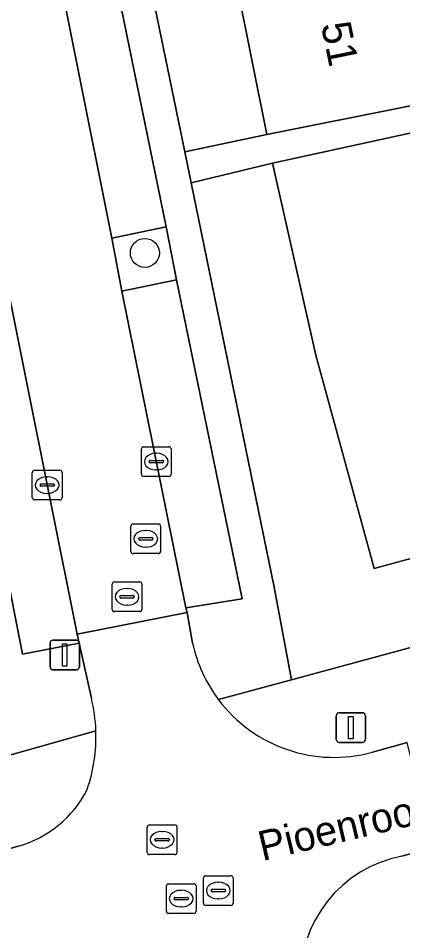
# Model space of a CAD drawing. Extents: x 162250 to 162661, y 380743 to 381606.
# Drawn here: x 162527.18 to 162540.15, y 380962.98 to 380993.72 of the extents above; entities that cross this region are included whole.
import ezdxf

# ---------------------------------------------------------------- set-up
doc = ezdxf.new("R2010")
doc.units = 0
for name, color, linetype in [('IMGEO_Boom', 7, 'Continuous'), ('IMGEO_Erf', 7, 'Continuous'), ('IMGEO_Groenvoorziening', 7, 'Continuous'), ('IMGEO_Kolk', 7, 'Continuous'), ('IMGEO_Lichtmast', 7, 'Continuous'), ('IMGEO_Openbare_ruimte_label', 7, 'Continuous'), ('IMGEO_Pand', 7, 'Continuous'), ('IMGEO_Pand_nummerreeks', 7, 'Continuous'), ('IMGEO_Parkeervlak_open', 7, 'Continuous'), ('IMGEO_Rijbaan_lokaal_open', 7, 'Continuous'), ('IMGEO_Rioolput', 7, 'Continuous'), ('IMGEO_Voetpad_open', 7, 'Continuous'), ('IMGEO_Woonerf_open', 7, 'Continuous')]:
    doc.layers.add(name, color=color, linetype=linetype)

msp = doc.modelspace()

# ---------------------------------------------------------------- linework, layer by layer
at = {"layer": 'IMGEO_Boom'}
msp.add_circle((162531.454, 380985.813), 0.489, dxfattribs=at)
at = {"layer": 'IMGEO_Erf'}
for points in [[(162522.143, 381040.929), (162529.31, 381005.466), (162530.582, 381000), (162532.797, 380989.217), (162535.562, 380989.8), (162534.55, 380994.844), (162533.553, 380999.816), (162533.516, 381000), (162532.586, 381004.64), (162531.573, 381009.689), (162531.896, 381009.754), (162530.915, 381014.622), (162529.951, 381019.403), (162528.936, 381024.444), (162528.01, 381029.037), (162527.714, 381028.978), (162526.67, 381034.16)], [(162584.66, 380993.815), (162584.129, 380993.669), (162585.707, 380987.946), (162575.368, 380985.129), (162568.351, 380983.216), (162563.435, 380981.877), (162558.558, 380980.548), (162558.309, 380980.48), (162558.21, 380980.844), (162553.71, 380979.617), (162548.909, 380978.309), (162549.03, 380977.865), (162544.039, 380976.505), (162543.728, 380976.42), (162539.181, 380975.181), (162537.223, 380982.367), (162535.754, 380988.839), (162533.01, 380988.176), (162535.808, 380974.554), (162536.403, 380971.431), (162590.435, 380986.089)]]:
    msp.add_lwpolyline(points, dxfattribs=at)
at = {"layer": 'IMGEO_Groenvoorziening'}
msp.add_lwpolyline([(162532.173, 380986.691), (162530.338, 380986.31), (162530.682, 380984.53), (162532.52, 380984.907)], close=True, dxfattribs=at)
at = {"layer": 'IMGEO_Kolk'}
for p, q in [((162531.338, 380978.358), (162531.338, 380979.21)), ((162531.413, 380979.284), (162532.265, 380979.284)), ((162532.339, 380979.21), (162532.339, 380978.358)), ((162531.597, 380978.778), (162531.597, 380978.79)), ((162531.64, 380978.827), (162532.038, 380978.827)), ((162531.826, 380979.064), (162531.851, 380979.064)), ((162532.081, 380978.79), (162532.081, 380978.778)), ((162527.735, 380978.495), (162528.587, 380978.495)), ((162532.035, 380978.741), (162531.637, 380978.741)), ((162531.849, 380978.504), (162531.824, 380978.504)), ((162527.66, 380977.569), (162527.66, 380978.421)), ((162528.148, 380978.275), (162528.173, 380978.275)), ((162528.661, 380978.421), (162528.661, 380977.569)), ((162532.265, 380978.284), (162531.413, 380978.284)), ((162527.919, 380977.989), (162527.919, 380978.001)), ((162528.357, 380977.952), (162527.959, 380977.952)), ((162527.962, 380978.038), (162528.36, 380978.038)), ((162528.403, 380978.001), (162528.403, 380977.989)), ((162528.171, 380977.715), (162528.146, 380977.715)), ((162528.587, 380977.495), (162527.735, 380977.495))]:
    msp.add_line(p, q, dxfattribs=at)
for points in [[(162531.338, 380978.358), (162531.338, 380979.21)], [(162531.413, 380979.284), (162532.265, 380979.284)], [(162532.339, 380979.21), (162532.339, 380978.358)], [(162527.735, 380978.495), (162528.587, 380978.495)], [(162527.66, 380977.569), (162527.66, 380978.421)], [(162528.661, 380978.421), (162528.661, 380977.569)], [(162532.265, 380978.284), (162531.413, 380978.284)], [(162528.587, 380977.495), (162527.735, 380977.495)]]:
    msp.add_lwpolyline(points, dxfattribs=at)
for centre, radius, start, end in [((162531.415, 380979.208), 0.0765, 91.552, 178.448), ((162531.415, 380979.208), 0.0765, 91.552, 178.448), ((162532.263, 380979.208), 0.0765, 1.552, 88.448), ((162532.263, 380979.208), 0.0765, 1.552, 88.448), ((162531.637, 380978.787), 0.0403, 85.8775, 175.7526), ((162532.042, 380978.789), 0.0386, 1.7309, 96.639), ((162527.737, 380978.419), 0.0765, 91.552, 178.448), ((162527.737, 380978.419), 0.0765, 91.552, 178.448), ((162528.585, 380978.419), 0.0765, 1.552, 88.448), ((162528.585, 380978.419), 0.0765, 1.552, 88.448), ((162531.634, 380978.777), 0.0366, 178.938, 274.7102), ((162532.038, 380978.784), 0.043, 264.8664, 352.4533), ((162531.415, 380978.36), 0.0765, 181.552, 268.448), ((162531.415, 380978.36), 0.0765, 181.552, 268.448), ((162532.263, 380978.36), 0.0765, 271.552, 358.448), ((162532.263, 380978.36), 0.0765, 271.552, 358.448), ((162527.959, 380977.998), 0.0403, 85.8775, 175.7526), ((162527.956, 380977.988), 0.0366, 178.938, 274.7102), ((162528.36, 380977.995), 0.043, 264.8664, 352.4533), ((162528.364, 380978), 0.0386, 1.7309, 96.639), ((162527.737, 380977.571), 0.0765, 181.552, 268.448), ((162527.737, 380977.571), 0.0765, 181.552, 268.448), ((162528.585, 380977.571), 0.0765, 271.552, 358.448), ((162528.585, 380977.571), 0.0765, 271.552, 358.448)]:
    msp.add_arc(centre, radius, start, end, dxfattribs=at)
for centre, major_axis, ratio, start_param, end_param in [((162531.825, 380978.784), (-0.387, 0.002), 0.722429, 4.712389, 7.853982), ((162531.85, 380978.784), (-0.39, 0.002), 0.717154, 1.570796, 4.712389), ((162528.147, 380977.995), (-0.387, 0.002), 0.722429, 4.712389, 7.853982), ((162528.172, 380977.995), (-0.39, 0.002), 0.717154, 1.570796, 4.712389)]:
    msp.add_ellipse(centre, major_axis=major_axis, ratio=ratio, start_param=start_param, end_param=end_param, dxfattribs=at)
at = {"layer": 'IMGEO_Lichtmast'}
for p, q in [((162528.256, 380971.872), (162528.256, 380972.672)), ((162528.256, 380972.672), (162528.256, 380971.872)), ((162528.356, 380972.772), (162529.146, 380972.772)), ((162529.146, 380972.772), (162528.356, 380972.772)), ((162529.246, 380972.672), (162529.246, 380971.872)), ((162529.246, 380971.872), (162529.246, 380972.672)), ((162529.146, 380971.772), (162528.356, 380971.772)), ((162528.356, 380971.772), (162529.146, 380971.772)), ((162537.903, 380969.425), (162537.903, 380970.225)), ((162537.903, 380970.225), (162537.903, 380969.425)), ((162538.003, 380970.325), (162538.793, 380970.325)), ((162538.793, 380970.325), (162538.003, 380970.325)), ((162538.893, 380970.225), (162538.893, 380969.425)), ((162538.893, 380969.425), (162538.893, 380970.225)), ((162538.793, 380969.325), (162538.003, 380969.325)), ((162538.003, 380969.325), (162538.793, 380969.325))]:
    msp.add_line(p, q, dxfattribs=at)
for points in [[(162528.676, 380972.647), (162528.826, 380972.647), (162528.826, 380971.897), (162528.676, 380971.897), (162528.676, 380972.647)], [(162538.323, 380970.2), (162538.473, 380970.2), (162538.473, 380969.45), (162538.323, 380969.45), (162538.323, 380970.2)]]:
    msp.add_lwpolyline(points, dxfattribs=at)
for centre, start, end in [((162528.356, 380972.672), 90, 180), ((162528.356, 380972.672), 90, 180), ((162529.146, 380972.672), 0, 90), ((162529.146, 380972.672), 360, 90), ((162528.356, 380971.872), 180, 270), ((162528.356, 380971.872), 180, 270), ((162529.146, 380971.872), 270, 0), ((162529.146, 380971.872), 270, 0), ((162538.003, 380970.225), 90, 180), ((162538.003, 380970.225), 90, 180), ((162538.793, 380970.225), 0, 90), ((162538.793, 380970.225), 360, 90), ((162538.003, 380969.425), 180, 270), ((162538.003, 380969.425), 180, 270), ((162538.793, 380969.425), 270, 0), ((162538.793, 380969.425), 270, 0)]:
    msp.add_arc(centre, 0.1, start, end, dxfattribs=at)
at = {"layer": 'IMGEO_Pand'}
for points in [[(162549.164, 380997.798), (162547.269, 380997.415), (162545.854, 380997.129), (162534.55, 380994.844), (162535.562, 380989.8), (162540.466, 380990.779), (162542.944, 380991.274), (162542.426, 380993.869), (162547.281, 380994.839), (162547.764, 380994.935), (162549.66, 380995.314)], [(162544.039, 380976.505), (162540.641, 380989.9), (162535.754, 380988.839), (162537.223, 380982.367), (162539.181, 380975.181), (162543.728, 380976.42)]]:
    msp.add_lwpolyline(points, close=True, dxfattribs=at)
at = {"layer": 'IMGEO_Parkeervlak_open'}
for points in [[(162530.338, 380986.31), (162532.173, 380986.691), (162529.751, 380998.475), (162527.982, 380998.093)], [(162529.238, 380972.673), (162529.173, 380972.977), (162526.498, 380986.245), (162524.664, 380985.878), (162527.328, 380972.293)], [(162534.731, 380974.16), (162532.52, 380984.907), (162530.682, 380984.53), (162532.831, 380973.854)]]:
    msp.add_lwpolyline(points, close=True, dxfattribs=at)
at = {"layer": 'IMGEO_Rijbaan_lokaal_open'}
for points in [[(162533.062, 380972.669), (162532.879, 380973.707), (162529.173, 380972.977), (162529.238, 380972.673), (162529.652, 380970.821)], [(162541.171, 380965.788), (162540.292, 380969.32), (162539.13, 380968.997)], [(162527.185, 380965.829), (162526.007, 380965.497), (162527.124, 380961.813), (162528.084, 380962.039)], [(162540.122, 380965.489), (162541.171, 380965.788)]]:
    msp.add_lwpolyline(points, dxfattribs=at)
for centre, radius, start, end in [((162537.82, 380973.7), 4.869, 192.2264, 217.0601), ((162524.301, 380969.522), 5.506, 2.0434, 13.6491), ((162537.835, 380973.707), 4.885, 217.0191, 285.3715), ((162524.291, 380969.532), 5.516, 341.0437, 1.9344), ((162526.182, 380969.415), 3.724, 285.6217, 333.2626), ((162540.883, 380961.376), 4.183, 100.4804, 182.5843)]:
    msp.add_arc(centre, radius, start, end, dxfattribs=at)
at = {"layer": 'IMGEO_Rioolput'}
for p, q in [((162531.06, 380976.684), (162531.912, 380976.684)), ((162530.985, 380975.758), (162530.985, 380976.61)), ((162531.473, 380976.464), (162531.498, 380976.464)), ((162531.986, 380976.61), (162531.986, 380975.758)), ((162531.244, 380976.178), (162531.244, 380976.19)), ((162531.682, 380976.141), (162531.284, 380976.141)), ((162531.287, 380976.227), (162531.685, 380976.227)), ((162531.728, 380976.19), (162531.728, 380976.178)), ((162531.496, 380975.904), (162531.471, 380975.904)), ((162531.912, 380975.684), (162531.06, 380975.684)), ((162530.354, 380973.804), (162530.354, 380974.656)), ((162530.429, 380974.73), (162531.281, 380974.73)), ((162530.842, 380974.51), (162530.867, 380974.51)), ((162531.355, 380974.656), (162531.355, 380973.804)), ((162530.613, 380974.224), (162530.613, 380974.236)), ((162531.051, 380974.187), (162530.653, 380974.187)), ((162530.656, 380974.273), (162531.054, 380974.273)), ((162531.097, 380974.236), (162531.097, 380974.224)), ((162530.865, 380973.95), (162530.84, 380973.95)), ((162531.281, 380973.73), (162530.429, 380973.73)), ((162531.611, 380966.549), (162532.463, 380966.549)), ((162531.536, 380965.623), (162531.536, 380966.475)), ((162532.024, 380966.329), (162532.049, 380966.329)), ((162532.537, 380966.475), (162532.537, 380965.623)), ((162531.795, 380966.043), (162531.795, 380966.055)), ((162532.233, 380966.006), (162531.835, 380966.006)), ((162531.838, 380966.092), (162532.236, 380966.092)), ((162532.279, 380966.055), (162532.279, 380966.043)), ((162532.047, 380965.769), (162532.022, 380965.769)), ((162532.463, 380965.549), (162531.611, 380965.549)), ((162533.429, 380963.909), (162533.429, 380964.761)), ((162533.504, 380964.835), (162534.356, 380964.835)), ((162534.43, 380964.761), (162534.43, 380963.909)), ((162532.178, 380963.638), (162532.178, 380964.49)), ((162532.253, 380964.564), (162533.105, 380964.564)), ((162532.666, 380964.344), (162532.691, 380964.344)), ((162533.179, 380964.49), (162533.179, 380963.638)), ((162533.688, 380964.329), (162533.688, 380964.341)), ((162533.731, 380964.378), (162534.129, 380964.378)), ((162533.917, 380964.615), (162533.942, 380964.615)), ((162534.172, 380964.341), (162534.172, 380964.329)), ((162532.437, 380964.058), (162532.437, 380964.07)), ((162532.48, 380964.107), (162532.878, 380964.107)), ((162532.921, 380964.07), (162532.921, 380964.058)), ((162534.126, 380964.292), (162533.728, 380964.292)), ((162533.94, 380964.055), (162533.915, 380964.055)), ((162532.875, 380964.021), (162532.477, 380964.021)), ((162532.689, 380963.784), (162532.664, 380963.784)), ((162534.356, 380963.835), (162533.504, 380963.835)), ((162533.105, 380963.564), (162532.253, 380963.564))]:
    msp.add_line(p, q, dxfattribs=at)
for points in [[(162531.06, 380976.684), (162531.912, 380976.684)], [(162530.985, 380975.758), (162530.985, 380976.61)], [(162531.986, 380976.61), (162531.986, 380975.758)], [(162531.912, 380975.684), (162531.06, 380975.684)], [(162530.354, 380973.804), (162530.354, 380974.656)], [(162530.429, 380974.73), (162531.281, 380974.73)], [(162531.355, 380974.656), (162531.355, 380973.804)], [(162531.281, 380973.73), (162530.429, 380973.73)], [(162531.611, 380966.549), (162532.463, 380966.549)], [(162531.536, 380965.623), (162531.536, 380966.475)], [(162532.537, 380966.475), (162532.537, 380965.623)], [(162532.463, 380965.549), (162531.611, 380965.549)], [(162533.429, 380963.909), (162533.429, 380964.761)], [(162533.504, 380964.835), (162534.356, 380964.835)], [(162534.43, 380964.761), (162534.43, 380963.909)], [(162532.178, 380963.638), (162532.178, 380964.49)], [(162532.253, 380964.564), (162533.105, 380964.564)], [(162533.179, 380964.49), (162533.179, 380963.638)], [(162534.356, 380963.835), (162533.504, 380963.835)], [(162533.105, 380963.564), (162532.253, 380963.564)]]:
    msp.add_lwpolyline(points, dxfattribs=at)
for centre, radius, start, end in [((162531.062, 380976.608), 0.0765, 91.552, 178.448), ((162531.062, 380976.608), 0.0765, 91.552, 178.448), ((162531.91, 380976.608), 0.0765, 1.552, 88.448), ((162531.91, 380976.608), 0.0765, 1.552, 88.448), ((162531.284, 380976.187), 0.0403, 85.8775, 175.7526), ((162531.281, 380976.177), 0.0366, 178.938, 274.7102), ((162531.685, 380976.184), 0.043, 264.8664, 352.4533), ((162531.689, 380976.189), 0.0386, 1.7309, 96.639), ((162531.062, 380975.76), 0.0765, 181.552, 268.448), ((162531.062, 380975.76), 0.0765, 181.552, 268.448), ((162531.91, 380975.76), 0.0765, 271.552, 358.448), ((162531.91, 380975.76), 0.0765, 271.552, 358.448), ((162530.431, 380974.654), 0.0765, 91.552, 178.448), ((162530.431, 380974.654), 0.0765, 91.552, 178.448), ((162531.279, 380974.654), 0.0765, 1.552, 88.448), ((162531.279, 380974.654), 0.0765, 1.552, 88.448), ((162530.653, 380974.233), 0.0403, 85.8775, 175.7526), ((162530.65, 380974.223), 0.0366, 178.938, 274.7102), ((162531.054, 380974.23), 0.043, 264.8664, 352.4533), ((162531.058, 380974.235), 0.0386, 1.7309, 96.639), ((162530.431, 380973.806), 0.0765, 181.552, 268.448), ((162530.431, 380973.806), 0.0765, 181.552, 268.448), ((162531.279, 380973.806), 0.0765, 271.552, 358.448), ((162531.279, 380973.806), 0.0765, 271.552, 358.448), ((162531.613, 380966.473), 0.0765, 91.552, 178.448), ((162531.613, 380966.473), 0.0765, 91.552, 178.448), ((162532.461, 380966.473), 0.0765, 1.552, 88.448), ((162532.461, 380966.473), 0.0765, 1.552, 88.448), ((162531.835, 380966.052), 0.0403, 85.8775, 175.7526), ((162531.832, 380966.042), 0.0366, 178.938, 274.7102), ((162532.236, 380966.049), 0.043, 264.8664, 352.4533), ((162532.24, 380966.054), 0.0386, 1.7309, 96.639), ((162531.613, 380965.625), 0.0765, 181.552, 268.448), ((162531.613, 380965.625), 0.0765, 181.552, 268.448), ((162532.461, 380965.625), 0.0765, 271.552, 358.448), ((162532.461, 380965.625), 0.0765, 271.552, 358.448), ((162533.506, 380964.759), 0.0765, 91.552, 178.448), ((162533.506, 380964.759), 0.0765, 91.552, 178.448), ((162534.354, 380964.759), 0.0765, 1.552, 88.448), ((162534.354, 380964.759), 0.0765, 1.552, 88.448), ((162532.255, 380964.488), 0.0765, 91.552, 178.448), ((162532.255, 380964.488), 0.0765, 91.552, 178.448), ((162533.103, 380964.488), 0.0765, 1.552, 88.448), ((162533.103, 380964.488), 0.0765, 1.552, 88.448), ((162533.728, 380964.338), 0.0403, 85.8775, 175.7526), ((162534.133, 380964.34), 0.0386, 1.7309, 96.639), ((162532.477, 380964.067), 0.0403, 85.8775, 175.7526), ((162532.474, 380964.057), 0.0366, 178.938, 274.7102), ((162532.878, 380964.064), 0.043, 264.8664, 352.4533), ((162532.882, 380964.069), 0.0386, 1.7309, 96.639), ((162533.725, 380964.328), 0.0366, 178.938, 274.7102), ((162534.129, 380964.335), 0.043, 264.8664, 352.4533), ((162533.506, 380963.911), 0.0765, 181.552, 268.448), ((162533.506, 380963.911), 0.0765, 181.552, 268.448), ((162534.354, 380963.911), 0.0765, 271.552, 358.448), ((162534.354, 380963.911), 0.0765, 271.552, 358.448), ((162532.255, 380963.64), 0.0765, 181.552, 268.448), ((162532.255, 380963.64), 0.0765, 181.552, 268.448), ((162533.103, 380963.64), 0.0765, 271.552, 358.448), ((162533.103, 380963.64), 0.0765, 271.552, 358.448)]:
    msp.add_arc(centre, radius, start, end, dxfattribs=at)
for centre, major_axis, ratio, start_param, end_param in [((162531.472, 380976.184), (-0.387, 0.002), 0.722429, 4.712389, 7.853982), ((162531.497, 380976.184), (-0.39, 0.002), 0.717154, 1.570796, 4.712389), ((162530.841, 380974.23), (-0.387, 0.002), 0.722429, 4.712389, 7.853982), ((162530.866, 380974.23), (-0.39, 0.002), 0.717154, 1.570796, 4.712389), ((162532.023, 380966.049), (-0.387, 0.002), 0.722429, 4.712389, 7.853982), ((162532.048, 380966.049), (-0.39, 0.002), 0.717154, 1.570796, 4.712389), ((162532.665, 380964.064), (-0.387, 0.002), 0.722429, 4.712389, 7.853982), ((162532.69, 380964.064), (-0.39, 0.002), 0.717154, 1.570796, 4.712389), ((162533.916, 380964.335), (-0.387, 0.002), 0.722429, 4.712389, 7.853982), ((162533.941, 380964.335), (-0.39, 0.002), 0.717154, 1.570796, 4.712389)]:
    msp.add_ellipse(centre, major_axis=major_axis, ratio=ratio, start_param=start_param, end_param=end_param, dxfattribs=at)
at = {"layer": 'IMGEO_Voetpad_open'}
for points in [[(162535.808, 380974.554), (162533.01, 380988.176), (162532.797, 380989.217), (162530.582, 381000), (162529.31, 381005.466), (162522.143, 381040.929), (162522.087, 381041.214), (162521.287, 381041.063), (162521.648, 381039.309), (162523.995, 381027.547), (162524.343, 381025.754), (162526.697, 381013.911), (162527.071, 381012.154), (162529.44, 381000.334), (162529.751, 380998.475), (162532.173, 380986.691), (162532.52, 380984.907), (162534.731, 380974.16), (162532.831, 380973.854), (162532.879, 380973.707), (162533.062, 380972.669)], [(162514.276, 381037.726), (162513.922, 381039.54), (162512.477, 381039.235), (162520.3, 381000), (162523.029, 380986.937), (162523.272, 380985.775), (162525.511, 380975.056), (162526.18, 380971.982), (162526.854, 380968.89), (162529.804, 380969.718)], [(162529.652, 380970.821), (162529.238, 380972.673), (162527.328, 380972.293), (162524.664, 380985.878), (162526.498, 380986.245), (162526.262, 380987.458), (162524.476, 380987.064), (162514.276, 381037.726)], [(162590.435, 380986.089), (162536.403, 380971.431), (162533.935, 380970.766)], [(162533.935, 380970.766), (162536.403, 380971.431), (162535.808, 380974.554)], [(162529.804, 380969.718), (162526.854, 380968.89), (162499.174, 380961.297), (162498.385, 380964.311)], [(162539.13, 380968.997), (162540.292, 380969.32)], [(162523.548, 380964.83), (162526.007, 380965.497), (162527.185, 380965.829)], [(162541.171, 380965.788), (162540.122, 380965.489)]]:
    msp.add_lwpolyline(points, dxfattribs=at)
msp.add_lwpolyline([(162552.705, 380992.782), (162557.567, 380993.649), (162560.053, 380994.327), (162562.41, 380994.969), (162564.759, 380995.716), (162564.606, 380996.74), (162556.31, 380994.716), (162555.014, 380994.529), (162552.05, 380993.767), (162542.944, 380991.274), (162540.466, 380990.779), (162535.562, 380989.8), (162532.797, 380989.217), (162533.01, 380988.176), (162535.754, 380988.839), (162540.641, 380989.9), (162543.044, 380990.421), (162547.922, 380991.479), (162550.347, 380992.14)], close=True, dxfattribs=at)
for centre, radius, start, end in [((162537.82, 380973.7), 4.869, 192.2264, 217.0601), ((162524.301, 380969.522), 5.506, 2.0434, 13.6491), ((162537.835, 380973.707), 4.885, 217.0191, 285.3715), ((162524.291, 380969.532), 5.516, 341.0437, 1.9344), ((162526.182, 380969.415), 3.724, 285.6217, 333.2626), ((162540.883, 380961.376), 4.183, 100.4804, 182.5843)]:
    msp.add_arc(centre, radius, start, end, dxfattribs=at)
at = {"layer": 'IMGEO_Woonerf_open'}
msp.add_lwpolyline([(162530.338, 380986.31), (162527.982, 380998.093), (162524.286, 380997.353), (162526.262, 380987.458), (162526.498, 380986.245), (162529.173, 380972.977), (162532.879, 380973.707), (162532.831, 380973.854), (162530.682, 380984.53)], close=True, dxfattribs=at)

# ---------------------------------------------------------------- texts
at = {"layer": 'IMGEO_Openbare_ruimte_label'}
msp.add_text('Pioenroosstraat', height=1, rotation=13.3553, dxfattribs=at).set_placement((162535.416, 380965.326))
at = {"layer": 'IMGEO_Pand_nummerreeks'}
msp.add_text('51', height=1, rotation=281.3444, dxfattribs=at).set_placement((162537.39, 380993.499))

doc.saveas('drawing.dxf')
